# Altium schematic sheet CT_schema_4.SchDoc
size 298 x 247 mm
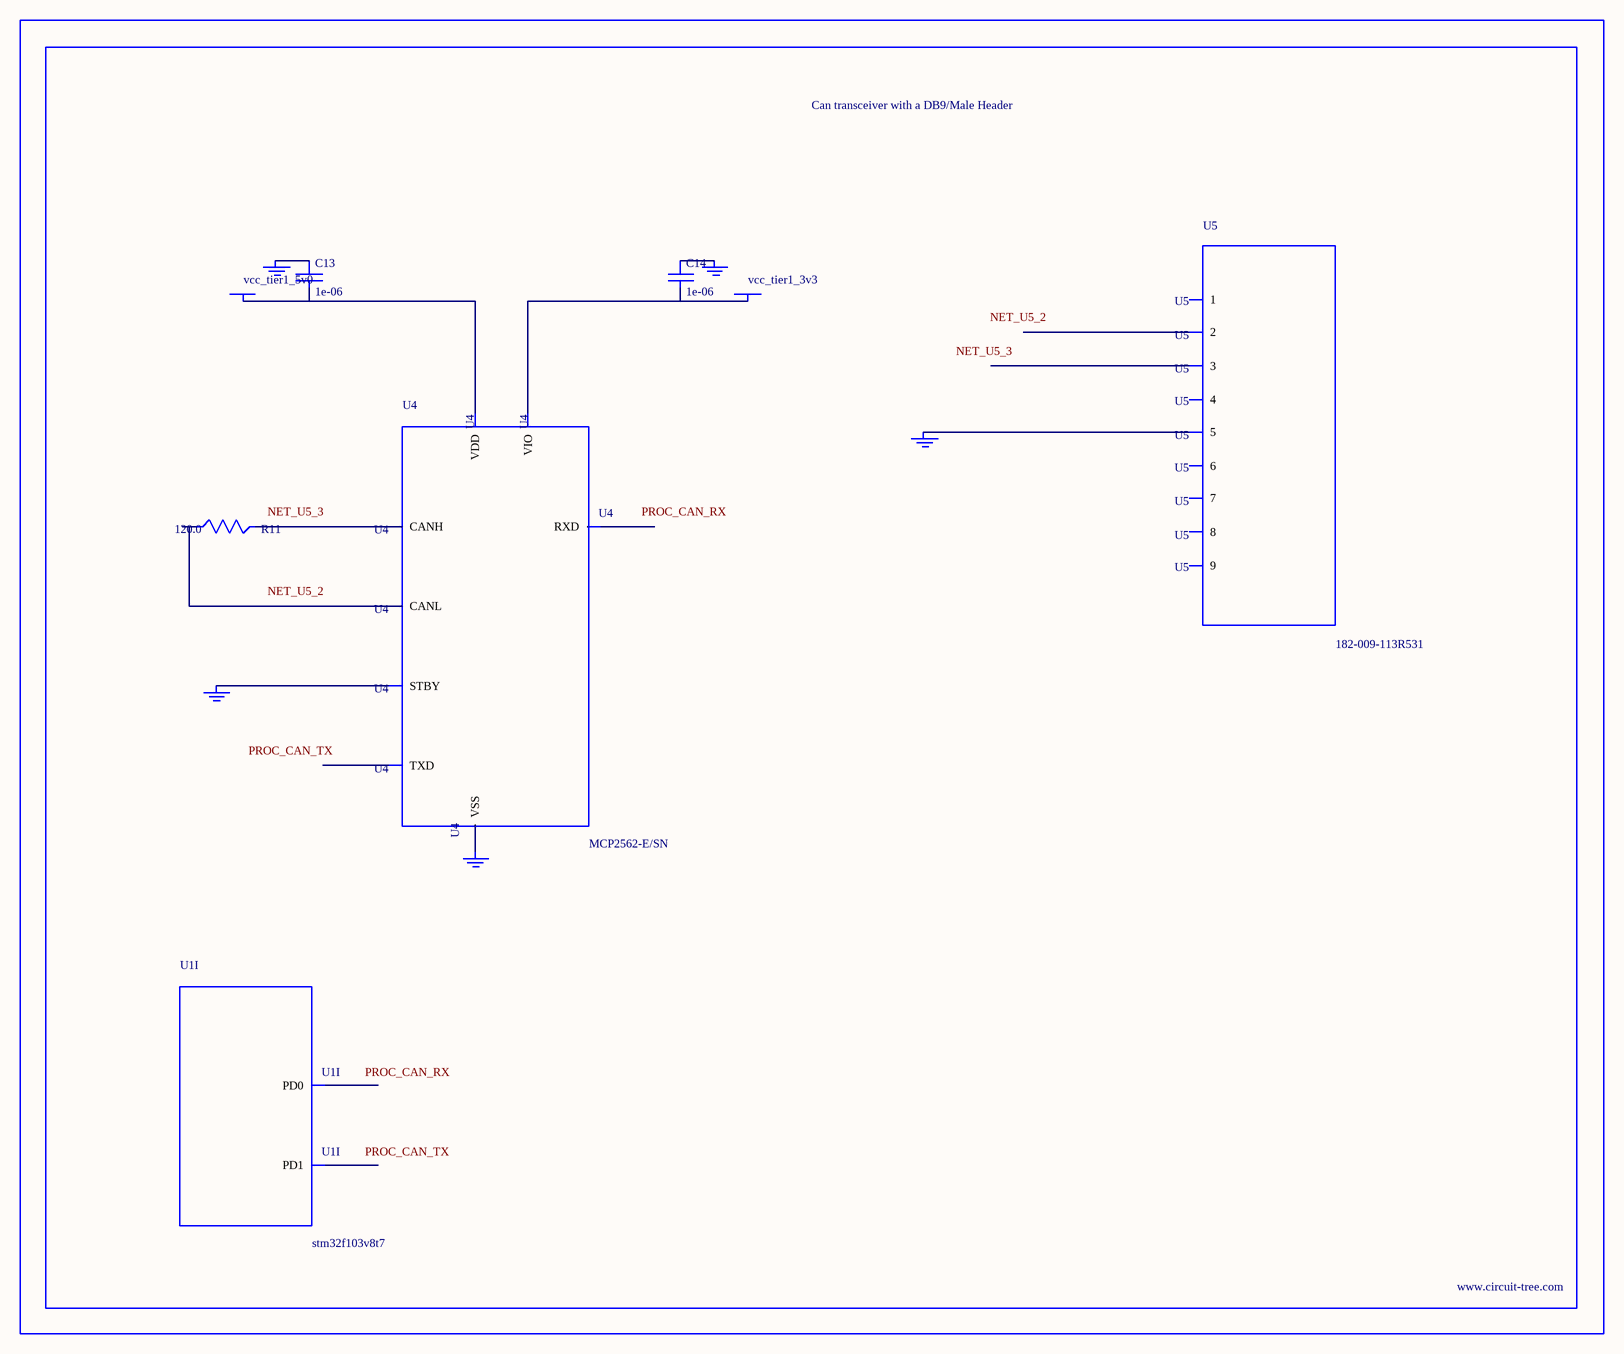
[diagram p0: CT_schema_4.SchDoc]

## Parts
BORDER3  (no value)
C13  1e-06  [C0603]
C14  1e-06  [C0603]
GND_INSTANCE_3_0  (no value)
GND_INSTANCE_3_1  (no value)
GND_INSTANCE_3_2  (no value)
GND_INSTANCE_3_3  (no value)
GND_INSTANCE_3_4  (no value)
POWER_INSTANCE_3_0  vcc_tier1_5v0
POWER_INSTANCE_3_1  vcc_tier1_3v3
R11  120.0  [R0603]
U1  stm32f103v8t7  [LQFP100]  (part I of 10)
U4  MCP2562-E/SN  [SOIC-8]
U5  182-009-113R531  [182-009-MALE]

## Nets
NetC13_1: C13.1 GND_INSTANCE_3_0.0(GND)
NetC13_2: C13.2 POWER_INSTANCE_3_0.0(PWR) U4.3(VDD)
NetC14_1: C14.1 GND_INSTANCE_3_1.0(GND)
NetC14_2: C14.2 POWER_INSTANCE_3_1.0(PWR) U4.5(VIO)
NetGND_INSTANCE_3_2_0: GND_INSTANCE_3_2.0(GND) U4.8(STBY)
NetGND_INSTANCE_3_3_0: GND_INSTANCE_3_3.0(GND) U4.2(VSS)
NetGND_INSTANCE_3_4_0: GND_INSTANCE_3_4.0(GND) U5.5
NetR11_1: R11.1 U4.6(CANL)
NetR11_2: R11.2 U4.7(CANH)

Not connected (* = marked no-connect by the designer): U1 81(PD0) 82(PD1); U4 1(TXD) 4(RXD); U5 1 2 3 4 6 7 8 9

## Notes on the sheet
- Labels drawn without touching a wire or pin: NET_U5_2, NET_U5_3, PROC_CAN_RX, PROC_CAN_TX

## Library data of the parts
BORDER3 = BORDER_PAGE3
C13 C14 = C0603C105K3RACTU
GND_INSTANCE_3_0-GND_INSTANCE_3_4 = GND
POWER_INSTANCE_3_0 POWER_INSTANCE_3_1 = PWR
R11 = RC0603JR-07120RL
